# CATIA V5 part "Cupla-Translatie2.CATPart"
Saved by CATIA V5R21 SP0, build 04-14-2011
Part number: Cupla T2
Bounding box of the stored display mesh (mm): x -110 to 100, y -100 to 100, z 0 to 330
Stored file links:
  C:\Users\MIRCEA\Desktop\PRRO\CATIAV5\Cupla-Translatie2.CATPart
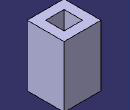
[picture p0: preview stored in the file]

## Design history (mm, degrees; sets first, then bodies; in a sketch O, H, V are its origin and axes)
Body1 (main body)
  Sketch1 on xy-plane, origin (0, 0, 0), H (1, 0, 0), V (0, 1, 0)
    line L1 (50, 50) -> (50, -50)
    line L2 (50, -50) -> (-50, -50)
    line L3 (-50, -50) -> (-50, 50)
    line L4 (-50, 50) -> (50, 50)
    point P2 (50, -50)
    line L5 (100, 100) -> (100, -100)
    line L6 (100, -100) -> (-100, -100)
    line L7 (-100, -100) -> (-100, 100)
    line L8 (-100, 100) -> (100, 100)
    distance L1 L3 = 100
    distance P2 H = 50
    distance L6 L8 = 200
    distance L5 L7 = 200
    vertical: L1 V, L3 V, L5 V, L7 V
    horizontal: L2 H, L4 H, L6 H, L8 H
    equidistance: L1 L3 O, L2 L4 O, L5 L7 O, L6 L8 O
  Pad1: profile Sketch1, direction (0, 0, 1), length 330
  Sketch2 on face of Pad1 from Sketch1.L7, origin (-100, 0, 0), H (0, -1, 0), V (0, 0, 1)
    circle A1 centre (0, 165) radius 40
    radius A1 = 40
  Pad2: profile Sketch2, direction (-1, 0, 0), length 10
